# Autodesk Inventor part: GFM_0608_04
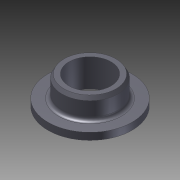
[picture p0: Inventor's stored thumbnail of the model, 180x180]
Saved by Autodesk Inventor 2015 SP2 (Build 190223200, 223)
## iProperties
Created: 2012-07
Part Number: GFM_0608_04
Material: PC/ABS-Kunststoff
Document SubType Name: Modeling
Designer: rYan
Mass: 0.224566 g
Surface Area: 3.47286 cm^2
Volume: 0.150412 cm^3
Density: 1.493 g/cm^3
Appearance: Glatt - schwarz
Übersetzungsnorm: STEP AP214IS
Dateiname: GFM_0608_04_1.stp
Vorprozessor: ACIS
Postprozessor: Build: 138, Release: 2013 RTM - Date: Thu 03/01/2012
Gesendete Einheiten: Millimeter
Unbestimmtheit: 1e-06
Author: rYan
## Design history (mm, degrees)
node "11"
node "1"
node "Basis1"
